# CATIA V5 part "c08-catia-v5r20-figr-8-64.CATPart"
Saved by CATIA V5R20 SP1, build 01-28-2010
Part number: Part1
Bounding box of the stored display mesh (mm): x -68.924 to 54.237, y -54.052 to 120.856, z 0 to 40
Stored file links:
  D:\v5_r20\psrt_files_downloaded\c08-catia-v5r20-prt\c08-catia-v5r20-figr-8-64.CATPart
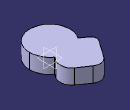
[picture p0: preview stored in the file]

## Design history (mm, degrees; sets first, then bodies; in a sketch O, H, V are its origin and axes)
Body1 (main body)
  Sketch1 on xy-plane, origin (0, 0, 0), H (1, 0, 0), V (0, 1, 0)
    circle A1 centre (0, 0) radius 54.2371
    point P1 (0, 54.2371)
    coincidence: A1 P1, P1 V
  Pad1: profile Sketch1, direction (0, 0, 1), length 40
  Body2
    Sketch2 on xy-plane, origin (0, 0, 0), H (1, 0, 0), V (0, 1, 0)
      line L1 (0, 0) -> (36.9865, 52.8223)
      arc A1 centre (11.6298, 70.5772) radius 30.9549 from (36.9865, 52.8223) to (29.3848, 95.934) ccw
      line L2 (29.3848, 95.934) -> (0.2008, 116.3688)
      arc A2 centre (-14.1853, 95.8234) radius 25.0814 from (0.2008, 116.3688) to (-34.7307, 110.2094) ccw
      line L3 (-34.7307, 110.2094) -> (-66.0893, 65.4248)
      arc A3 centre (-53.2403, 56.4279) radius 15.6856 from (-66.0893, 65.4248) to (-62.2373, 43.579) ccw
      line L4 (-62.2373, 43.579) -> (0, 0)
      tangency: A1 L1, L2 A1, A2 L2, L3 A2, A3 L3, L4 A3
    Pad2: profile Sketch2, direction (0, 0, 1), length 40
  Add1: tool Body2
